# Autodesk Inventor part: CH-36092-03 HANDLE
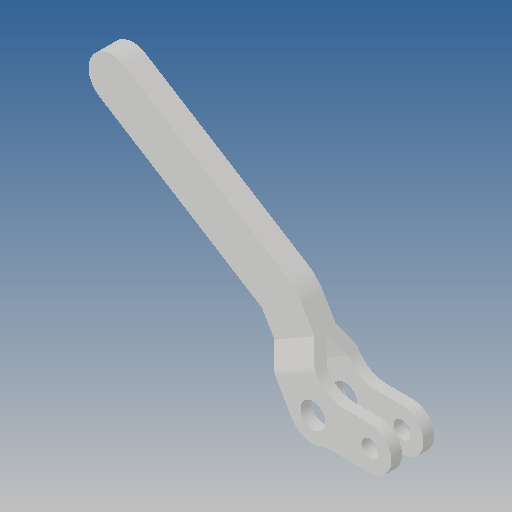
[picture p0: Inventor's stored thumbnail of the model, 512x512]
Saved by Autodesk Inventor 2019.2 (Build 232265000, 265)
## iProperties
Created: 2012-09
Part Number: CH-36092-03 HANDLE
Material: Ogólny
Document SubType Name: Modeling
Designer: CADENGINEERING4
Density: 1 g/cm^3
Appearance: Domyślna
Author: CADENGINEERING4
Revision Number: ÈÎºÎ
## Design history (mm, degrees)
feature "ÇÐ³ý-À­Éì4"
feature "¾µÏò1"
node "Bryła1"
node "Bryła2"
